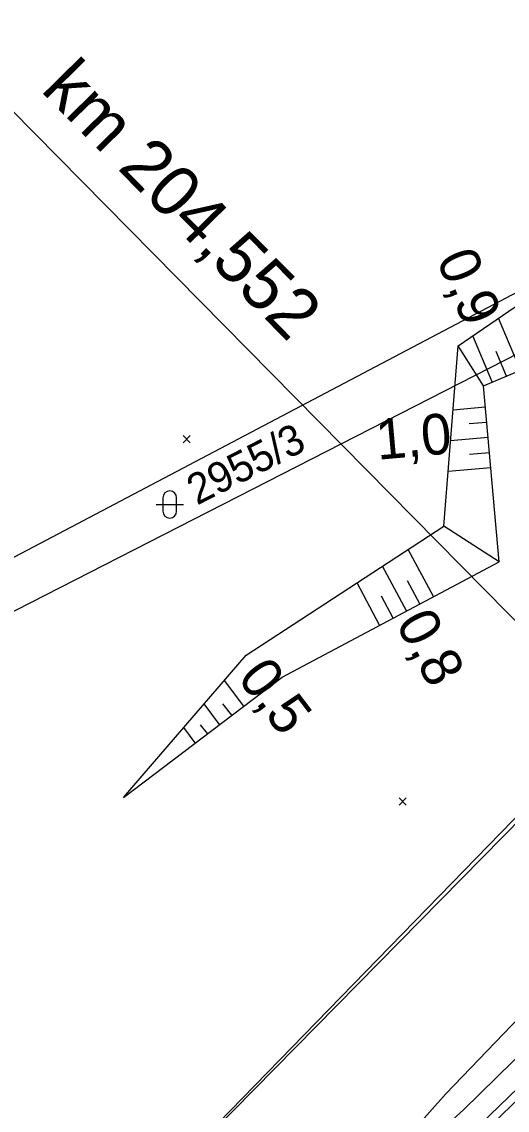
# Model space of a CAD drawing. Extents: x -800194 to -799078, y -1007177 to -1006597.
# Drawn here: x -799466.4 to -799442.5, y -1006906.9 to -1006853.3 of the extents above; entities that cross this region are included whole.
import ezdxf

# ---------------------------------------------------------------- set-up
doc = ezdxf.new("R2010")
doc.units = 0
for name, color, linetype in [('Vrstva 4', 7, 'Continuous'), ('Vrstva 48', 7, 'Continuous'), ('Vrstva 49', 7, 'Continuous'), ('Vrstva 5', 7, 'Continuous'), ('Vrstva 53', 7, 'Continuous'), ('Vrstva 55', 7, 'Continuous'), ('Vrstva 57', 7, 'Continuous'), ('Vrstva 58', 7, 'Continuous')]:
    doc.layers.add(name, color=color, linetype=linetype)

msp = doc.modelspace()

# ---------------------------------------------------------------- linework, layer by layer
at = {"layer": 'Vrstva 4'}
for points in [[(-799510.394, -1006958.536), (-799498.027, -1006951.328), (-799477.988, -1006937.435), (-799460.33, -1006923.117), (-799451.862, -1006915.581), (-799443.604, -1006907.9), (-799435.444, -1006900.067), (-799428.64, -1006893.299), (-799422.817, -1006887.511), (-799415.998, -1006880.595), (-799408.158, -1006872.652), (-799401.02, -1006864.85)], [(-799511.236, -1006957.129), (-799499.236, -1006950.771), (-799498.598, -1006949.914), (-799498.679, -1006949.705), (-799496.151, -1006948.479), (-799496.251, -1006948.258), (-799490.687, -1006944.683), (-799490.497, -1006944.878), (-799488.249, -1006943.052), (-799488.105, -1006943.216), (-799486.269, -1006941.68), (-799478.997, -1006936.484), (-799474.568, -1006932.916), (-799474.237, -1006932.694), (-799461.519, -1006921.99), (-799452.935, -1006914.372), (-799444.695, -1006906.886), (-799436.579, -1006898.932), (-799429.629, -1006892.192), (-799429.07, -1006892.727), (-799423.479, -1006886.901), (-799416.56, -1006880.007), (-799417.085, -1006879.46), (-799415.349, -1006878.386)], [(-799510.726, -1006958.045), (-799497.901, -1006950.516), (-799478.36, -1006937.055), (-799461.534, -1006923.53), (-799452.128, -1006915.305), (-799443.894, -1006907.632), (-799435.739, -1006899.754), (-799428.922, -1006893.007), (-799423.223, -1006887.256), (-799416.277, -1006880.269), (-799414.896, -1006878.87)]]:
    msp.add_lwpolyline(points, dxfattribs=at)
at = {"layer": 'Vrstva 48'}
for p, q in [((-799441.897, -1006870.468), (-799442.971, -1006867.903)), ((-799443.28, -1006871.048), (-799444.235, -1006868.768)), ((-799442.588, -1006870.758), (-799443.096, -1006869.547)), ((-799443.626, -1006872.289), (-799445.215, -1006872.43)), ((-799443.56, -1006873.036), (-799444.417, -1006873.112)), ((-799443.494, -1006873.783), (-799445.333, -1006873.946)), ((-799443.427, -1006874.53), (-799444.41, -1006874.617)), ((-799443.361, -1006875.277), (-799445.451, -1006875.463)), ((-799446.183, -1006881.617), (-799447.42, -1006879.29)), ((-799447.507, -1006882.321), (-799448.681, -1006880.114)), ((-799448.832, -1006883.025), (-799449.942, -1006880.937)), ((-799446.845, -1006881.969), (-799447.448, -1006880.835)), ((-799448.169, -1006882.673), (-799448.74, -1006881.599)), ((-799455.512, -1006887.006), (-799456.472, -1006885.742)), ((-799456.707, -1006887.913), (-799457.474, -1006886.903)), ((-799456.11, -1006887.459), (-799456.541, -1006886.891)), ((-799457.902, -1006888.82), (-799458.475, -1006888.065)), ((-799457.304, -1006888.366), (-799457.639, -1006887.925))]:
    msp.add_line(p, q, dxfattribs=at)
at = {"layer": 'Vrstva 49'}
for p, q in [((-799443.72, -1006871.232), (-799444.968, -1006869.269)), ((-799458.508, -1006873.685), (-799458.154, -1006874.039)), ((-799458.508, -1006874.039), (-799458.154, -1006873.685)), ((-799442.951, -1006879.899), (-799445.66, -1006878.142)), ((-799447.872, -1006891.527), (-799447.518, -1006891.881)), ((-799447.872, -1006891.881), (-799447.518, -1006891.527))]:
    msp.add_line(p, q, dxfattribs=at)
for points in [[(-799461.444, -1006891.51), (-799455.403, -1006884.501), (-799445.66, -1006878.142), (-799444.968, -1006869.269), (-799439.353, -1006865.427)], [(-799461.444, -1006891.51), (-799453.63, -1006885.576), (-799442.951, -1006879.899), (-799443.72, -1006871.232), (-799441.503, -1006870.303)], [(-799429.125, -1006891.656), (-799433.133, -1006889.484), (-799437.572, -1006888.963), (-799439.693, -1006890.332), (-799461.15, -1006912.135), (-799487.142, -1006929.222), (-799487.006, -1006931.546), (-799490.308, -1006935.771)], [(-799490.09, -1006944.145), (-799488.194, -1006942.597), (-799488.011, -1006942.815), (-799488.011, -1006942.815), (-799486.419, -1006941.508), (-799486.269, -1006941.68), (-799484.618, -1006939.109), (-799474.926, -1006932.405), (-799474.596, -1006932.171), (-799461.519, -1006921.99), (-799452.935, -1006914.372), (-799445.566, -1006906.106), (-799432.588, -1006892.596), (-799429.125, -1006891.656)]]:
    msp.add_lwpolyline(points, dxfattribs=at)
at = {"layer": 'Vrstva 5'}
msp.add_line((-799466.989, -1006857.616), (-799431.886, -1006893.222), dxfattribs=at)
at = {"layer": 'Vrstva 53'}
msp.add_lwpolyline([(-799559.64, -1006968.48), (-799519.68, -1006952.01), (-799500.87, -1006940.41), (-799496.64, -1006937.8), (-799494.85, -1006936.7), (-799484.519, -1006930.319), (-799457.99, -1006908.8), (-799435, -1006885.17), (-799430.26, -1006880.27), (-799425.53, -1006875.38), (-799422.55, -1006864.36), (-799390.88, -1006834), (-799358.35, -1006806.65), (-799352.29, -1006801.56), (-799330.91, -1006783.58), (-799314.235, -1006766.649)], dxfattribs=at)
at = {"layer": 'Vrstva 55'}
for points in [[(-799498.58, -1006896.8), (-799468.62, -1006880.61), (-799439.23, -1006865.13)], [(-799439.06, -1006868.14), (-799466.75, -1006882.3), (-799482.8, -1006890.48), (-799499.57, -1006898.99), (-799506.49, -1006901.85)], [(-799494.85, -1006936.7), (-799484.52, -1006930.32), (-799457.99, -1006908.8), (-799435, -1006885.17)]]:
    msp.add_lwpolyline(points, dxfattribs=at)
at = {"layer": 'Vrstva 58'}
for p, q in [((-799459.495, -1006876.745), (-799459.495, -1006877.416)), ((-799458.825, -1006877.416), (-799458.825, -1006876.745)), ((-799459.831, -1006877.081), (-799458.489, -1006877.081))]:
    msp.add_line(p, q, dxfattribs=at)
for centre, start, end in [((-799459.16, -1006876.746), 0, 180), ((-799459.16, -1006877.416), 180, 359.9879)]:
    msp.add_arc(centre, 0.335, start, end, dxfattribs=at)

# ---------------------------------------------------------------- texts
at = {"layer": 'Vrstva 48'}
for s, rotation, p in [('0,9', 292.7354, (-799446.054, -1006865.002)), ('1,0', 5.0704, (-799448.924, -1006874.881)), ('0,8', 297.9953, (-799448.066, -1006882.927)), ('0,5', 307.2133, (-799455.873, -1006885.628))]:
    msp.add_text(s, height=2, rotation=rotation, dxfattribs=at).set_placement(p)
at = {"layer": 'Vrstva 5'}
msp.add_text('km 204,552', height=2.5, rotation=314.5927, dxfattribs=at).set_placement((-799465.555, -1006856.698))
at = {"layer": 'Vrstva 57'}
msp.add_text('2955/3', height=1.5, rotation=27, dxfattribs=at).set_placement((-799457.82, -1006877.138))

doc.saveas('drawing.dxf')
